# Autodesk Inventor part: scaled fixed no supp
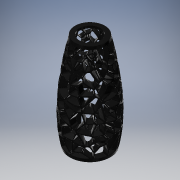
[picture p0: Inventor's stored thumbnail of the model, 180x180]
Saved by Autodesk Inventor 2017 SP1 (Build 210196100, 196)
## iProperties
Created: 2016-12
Part Number: scaled fixed no supp
Material: Generic
Document SubType Name: Modeling
Designer: HP_ELITE
Density: 1 g/cm^3
Appearance: Default
Author: HP_ELITE
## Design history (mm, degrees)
node "scaled fixed no supp"
  node "MeshFeature1"
body "Solid1"
